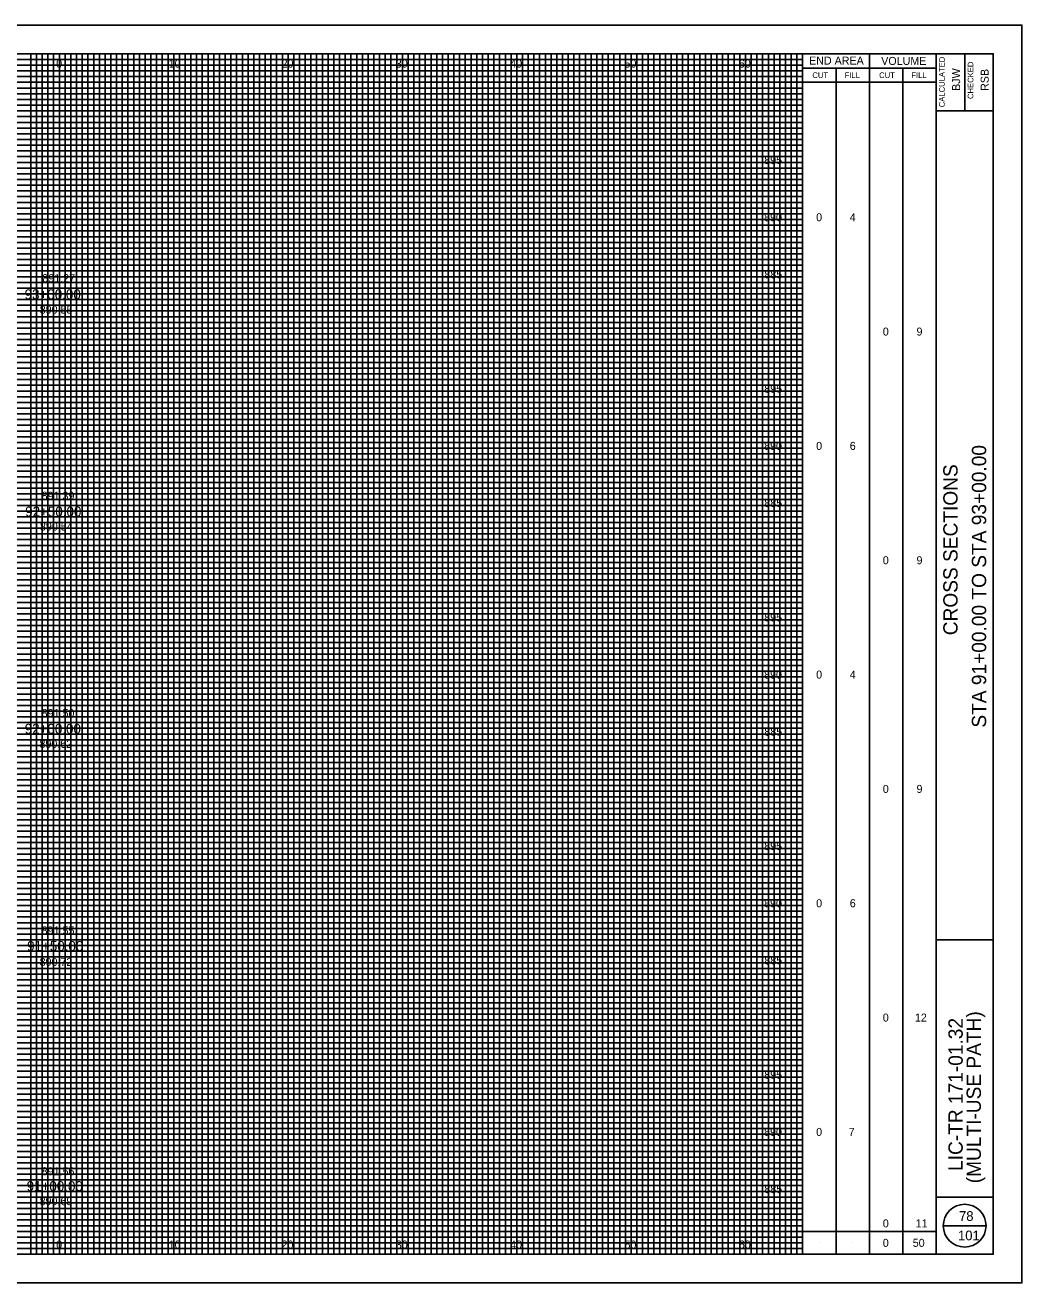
# Model space of a CAD drawing. Extents: x -10 to 160, y -2 to 3672.
# Drawn here: x 72.8 to 160, y 1032.5 to 1142.5 of the extents above; entities that cross this region are included whole.
import ezdxf

# ---------------------------------------------------------------- set-up
doc = ezdxf.new("R2010")
doc.units = 0
for name, color, linetype in [('SH_Border', 7, 'Continuous'), ('SH_Cut_Line', 7, 'Continuous'), ('SH_Data', 7, 'Continuous'), ('SH_Major_Grid_Line', 7, 'Continuous'), ('SH_Minor_Grid_Line', 7, 'Continuous'), ('SH_Text', 7, 'Continuous'), ('TX_P_10', 7, 'Continuous'), ('TX_X_10', 7, 'Continuous')]:
    doc.layers.add(name, color=color, linetype=linetype)

msp = doc.modelspace()

# ---------------------------------------------------------------- linework, layer by layer
at = {"layer": 'SH_Border'}
for p, q in [((152.5, 1035), (152.5, 1140)), ((155, 1140), (155, 1135)), ((152.5, 1135), (157.5, 1135)), ((152.5, 1062.5), (157.5, 1062.5)), ((152.5, 1040), (157.5, 1040))]:
    msp.add_line(p, q, dxfattribs=at)
msp.add_lwpolyline([(0, 1140), (157.5, 1140), (157.5, 1035), (0, 1035)], close=True, dxfattribs=at)
at = {"layer": 'SH_Cut_Line'}
msp.add_lwpolyline([(-10, 1032.5), (160, 1032.5), (160, 1142.5), (-10, 1142.5)], close=True, dxfattribs=at)
at = {"layer": 'SH_Data'}
for p, q in [((140.83, 1035), (140.83, 1140)), ((146.67, 1035), (146.67, 1140)), ((140.83, 1138.75), (152.5, 1138.75)), ((143.75, 1035), (143.75, 1138.75)), ((149.58, 1035), (149.58, 1138.75)), ((140.83, 1137.5), (152.5, 1137.5)), ((153.12, 1037.5), (156.88, 1037.5)), ((140.83, 1037), (152.5, 1037)), ((142.29, 1036), (142.29, 1036)), ((145.21, 1036), (145.21, 1036)), ((148.12, 1036), (148.12, 1036)), ((151.04, 1036), (151.04, 1036))]:
    msp.add_line(p, q, dxfattribs=at)
msp.add_circle((155, 1037.5), 1.87, dxfattribs=at)
at = {"layer": 'SH_Major_Grid_Line'}
for p, q in [((75.83, 1035), (75.83, 1140)), ((80.83, 1035), (80.83, 1140)), ((85.83, 1035), (85.83, 1140)), ((90.83, 1035), (90.83, 1140)), ((95.83, 1035), (95.83, 1140)), ((100.83, 1035), (100.83, 1140)), ((105.83, 1035), (105.83, 1140)), ((110.83, 1035), (110.83, 1140)), ((115.83, 1035), (115.83, 1140)), ((120.83, 1035), (120.83, 1140)), ((125.83, 1035), (125.83, 1140)), ((130.83, 1035), (130.83, 1140)), ((135.83, 1035), (135.83, 1140)), ((5.83, 1135), (140.83, 1135)), ((5.83, 1130), (140.83, 1130)), ((5.83, 1125), (140.83, 1125)), ((5.83, 1120), (140.83, 1120)), ((5.83, 1115), (140.83, 1115)), ((5.83, 1110), (140.83, 1110)), ((5.83, 1105), (140.83, 1105)), ((5.83, 1100), (140.83, 1100)), ((5.83, 1095), (140.83, 1095)), ((5.83, 1090), (140.83, 1090)), ((5.83, 1085), (140.83, 1085)), ((5.83, 1080), (140.83, 1080)), ((5.83, 1075), (140.83, 1075)), ((5.83, 1070), (140.83, 1070)), ((5.83, 1065), (140.83, 1065)), ((5.83, 1060), (140.83, 1060)), ((5.83, 1055), (140.83, 1055)), ((5.83, 1050), (140.83, 1050)), ((5.83, 1045), (140.83, 1045)), ((5.83, 1040), (140.83, 1040))]:
    msp.add_line(p, q, dxfattribs=at)
at = {"layer": 'SH_Minor_Grid_Line'}
for p, q in [((73.33, 1035), (73.33, 1140)), ((73.83, 1035), (73.83, 1140)), ((74.33, 1035), (74.33, 1140)), ((74.83, 1035), (74.83, 1140)), ((75.33, 1035), (75.33, 1140)), ((76.33, 1035), (76.33, 1140)), ((76.83, 1035), (76.83, 1140)), ((77.33, 1035), (77.33, 1140)), ((77.83, 1035), (77.83, 1140)), ((78.33, 1035), (78.33, 1140)), ((78.83, 1035), (78.83, 1140)), ((79.33, 1035), (79.33, 1140)), ((79.83, 1035), (79.83, 1140)), ((80.33, 1035), (80.33, 1140)), ((81.33, 1035), (81.33, 1140)), ((81.83, 1035), (81.83, 1140)), ((82.33, 1035), (82.33, 1140)), ((82.83, 1035), (82.83, 1140)), ((83.33, 1035), (83.33, 1140)), ((83.83, 1035), (83.83, 1140)), ((84.33, 1035), (84.33, 1140)), ((84.83, 1035), (84.83, 1140)), ((85.33, 1035), (85.33, 1140)), ((86.33, 1035), (86.33, 1140)), ((86.83, 1035), (86.83, 1140)), ((87.33, 1035), (87.33, 1140)), ((87.83, 1035), (87.83, 1140)), ((88.33, 1035), (88.33, 1140)), ((88.83, 1035), (88.83, 1140)), ((89.33, 1035), (89.33, 1140)), ((89.83, 1035), (89.83, 1140)), ((90.33, 1035), (90.33, 1140)), ((91.33, 1035), (91.33, 1140)), ((91.83, 1035), (91.83, 1140)), ((92.33, 1035), (92.33, 1140)), ((92.83, 1035), (92.83, 1140)), ((93.33, 1035), (93.33, 1140)), ((93.83, 1035), (93.83, 1140)), ((94.33, 1035), (94.33, 1140)), ((94.83, 1035), (94.83, 1140)), ((95.33, 1035), (95.33, 1140)), ((96.33, 1035), (96.33, 1140)), ((96.83, 1035), (96.83, 1140)), ((97.33, 1035), (97.33, 1140)), ((97.83, 1035), (97.83, 1140)), ((98.33, 1035), (98.33, 1140)), ((98.83, 1035), (98.83, 1140)), ((99.33, 1035), (99.33, 1140)), ((99.83, 1035), (99.83, 1140)), ((100.33, 1035), (100.33, 1140)), ((101.33, 1035), (101.33, 1140)), ((101.83, 1035), (101.83, 1140)), ((102.33, 1035), (102.33, 1140)), ((102.83, 1035), (102.83, 1140)), ((103.33, 1035), (103.33, 1140)), ((103.83, 1035), (103.83, 1140)), ((104.33, 1035), (104.33, 1140)), ((104.83, 1035), (104.83, 1140)), ((105.33, 1035), (105.33, 1140)), ((106.33, 1035), (106.33, 1140)), ((106.83, 1035), (106.83, 1140)), ((107.33, 1035), (107.33, 1140)), ((107.83, 1035), (107.83, 1140)), ((108.33, 1035), (108.33, 1140)), ((108.83, 1035), (108.83, 1140)), ((109.33, 1035), (109.33, 1140)), ((109.83, 1035), (109.83, 1140)), ((110.33, 1035), (110.33, 1140)), ((111.33, 1035), (111.33, 1140)), ((111.83, 1035), (111.83, 1140)), ((112.33, 1035), (112.33, 1140)), ((112.83, 1035), (112.83, 1140)), ((113.33, 1035), (113.33, 1140)), ((113.83, 1035), (113.83, 1140)), ((114.33, 1035), (114.33, 1140)), ((114.83, 1035), (114.83, 1140)), ((115.33, 1035), (115.33, 1140)), ((116.33, 1035), (116.33, 1140)), ((116.83, 1035), (116.83, 1140)), ((117.33, 1035), (117.33, 1140)), ((117.83, 1035), (117.83, 1140)), ((118.33, 1035), (118.33, 1140)), ((118.83, 1035), (118.83, 1140)), ((119.33, 1035), (119.33, 1140)), ((119.83, 1035), (119.83, 1140)), ((120.33, 1035), (120.33, 1140)), ((121.33, 1035), (121.33, 1140)), ((121.83, 1035), (121.83, 1140)), ((122.33, 1035), (122.33, 1140)), ((122.83, 1035), (122.83, 1140)), ((123.33, 1035), (123.33, 1140)), ((123.83, 1035), (123.83, 1140)), ((124.33, 1035), (124.33, 1140)), ((124.83, 1035), (124.83, 1140)), ((125.33, 1035), (125.33, 1140)), ((126.33, 1035), (126.33, 1140)), ((126.83, 1035), (126.83, 1140)), ((127.33, 1035), (127.33, 1140)), ((127.83, 1035), (127.83, 1140)), ((128.33, 1035), (128.33, 1140)), ((128.83, 1035), (128.83, 1140)), ((129.33, 1035), (129.33, 1140)), ((129.83, 1035), (129.83, 1140)), ((130.33, 1035), (130.33, 1140)), ((131.33, 1035), (131.33, 1140)), ((131.83, 1035), (131.83, 1140)), ((132.33, 1035), (132.33, 1140)), ((132.83, 1035), (132.83, 1140)), ((133.33, 1035), (133.33, 1140)), ((133.83, 1035), (133.83, 1140)), ((134.33, 1035), (134.33, 1140)), ((134.83, 1035), (134.83, 1140)), ((135.33, 1035), (135.33, 1140)), ((136.33, 1035), (136.33, 1140)), ((136.83, 1035), (136.83, 1140)), ((137.33, 1035), (137.33, 1140)), ((137.83, 1035), (137.83, 1140)), ((138.33, 1035), (138.33, 1140)), ((138.83, 1035), (138.83, 1140)), ((139.33, 1035), (139.33, 1140)), ((139.83, 1035), (139.83, 1140)), ((140.33, 1035), (140.33, 1140)), ((5.83, 1139.5), (140.83, 1139.5)), ((5.83, 1139), (140.83, 1139)), ((5.83, 1138.5), (140.83, 1138.5)), ((5.83, 1138), (140.83, 1138)), ((5.83, 1137.5), (140.83, 1137.5)), ((5.83, 1137), (140.83, 1137)), ((5.83, 1136.5), (140.83, 1136.5)), ((5.83, 1136), (140.83, 1136)), ((5.83, 1135.5), (140.83, 1135.5)), ((5.83, 1134.5), (140.83, 1134.5)), ((5.83, 1134), (140.83, 1134)), ((5.83, 1133.5), (140.83, 1133.5)), ((5.83, 1133), (140.83, 1133)), ((5.83, 1132.5), (140.83, 1132.5)), ((5.83, 1132), (140.83, 1132)), ((5.83, 1131.5), (140.83, 1131.5)), ((5.83, 1131), (140.83, 1131)), ((5.83, 1130.5), (140.83, 1130.5)), ((5.83, 1129.5), (140.83, 1129.5)), ((5.83, 1129), (140.83, 1129)), ((5.83, 1128.5), (140.83, 1128.5)), ((5.83, 1128), (140.83, 1128)), ((5.83, 1127.5), (140.83, 1127.5)), ((5.83, 1127), (140.83, 1127)), ((5.83, 1126.5), (140.83, 1126.5)), ((5.83, 1126), (140.83, 1126)), ((5.83, 1125.5), (140.83, 1125.5)), ((5.83, 1124.5), (140.83, 1124.5)), ((5.83, 1124), (140.83, 1124)), ((5.83, 1123.5), (140.83, 1123.5)), ((5.83, 1123), (140.83, 1123)), ((5.83, 1122.5), (140.83, 1122.5)), ((5.83, 1122), (140.83, 1122)), ((5.83, 1121.5), (140.83, 1121.5)), ((5.83, 1121), (140.83, 1121)), ((5.83, 1120.5), (140.83, 1120.5)), ((5.83, 1119.5), (140.83, 1119.5)), ((5.83, 1119), (140.83, 1119)), ((5.83, 1118.5), (140.83, 1118.5)), ((5.83, 1118), (140.83, 1118)), ((5.83, 1117.5), (140.83, 1117.5)), ((5.83, 1117), (140.83, 1117)), ((5.83, 1116.5), (140.83, 1116.5)), ((5.83, 1116), (140.83, 1116)), ((5.83, 1115.5), (140.83, 1115.5)), ((5.83, 1114.5), (140.83, 1114.5)), ((5.83, 1114), (140.83, 1114)), ((5.83, 1113.5), (140.83, 1113.5)), ((5.83, 1113), (140.83, 1113)), ((5.83, 1112.5), (140.83, 1112.5)), ((5.83, 1112), (140.83, 1112)), ((5.83, 1111.5), (140.83, 1111.5)), ((5.83, 1111), (140.83, 1111)), ((5.83, 1110.5), (140.83, 1110.5)), ((5.83, 1109.5), (140.83, 1109.5)), ((5.83, 1109), (140.83, 1109)), ((5.83, 1108.5), (140.83, 1108.5)), ((5.83, 1108), (140.83, 1108)), ((5.83, 1107.5), (140.83, 1107.5)), ((5.83, 1107), (140.83, 1107)), ((5.83, 1106.5), (140.83, 1106.5)), ((5.83, 1106), (140.83, 1106)), ((5.83, 1105.5), (140.83, 1105.5)), ((5.83, 1104.5), (140.83, 1104.5)), ((5.83, 1104), (140.83, 1104)), ((5.83, 1103.5), (140.83, 1103.5)), ((5.83, 1103), (140.83, 1103)), ((5.83, 1102.5), (140.83, 1102.5)), ((5.83, 1102), (140.83, 1102)), ((5.83, 1101.5), (140.83, 1101.5)), ((5.83, 1101), (140.83, 1101)), ((5.83, 1100.5), (140.83, 1100.5)), ((5.83, 1099.5), (140.83, 1099.5)), ((5.83, 1099), (140.83, 1099)), ((5.83, 1098.5), (140.83, 1098.5)), ((5.83, 1098), (140.83, 1098)), ((5.83, 1097.5), (140.83, 1097.5)), ((5.83, 1097), (140.83, 1097)), ((5.83, 1096.5), (140.83, 1096.5)), ((5.83, 1096), (140.83, 1096)), ((5.83, 1095.5), (140.83, 1095.5)), ((5.83, 1094.5), (140.83, 1094.5)), ((5.83, 1094), (140.83, 1094)), ((5.83, 1093.5), (140.83, 1093.5)), ((5.83, 1093), (140.83, 1093)), ((5.83, 1092.5), (140.83, 1092.5)), ((5.83, 1092), (140.83, 1092)), ((5.83, 1091.5), (140.83, 1091.5)), ((5.83, 1091), (140.83, 1091)), ((5.83, 1090.5), (140.83, 1090.5)), ((5.83, 1089.5), (140.83, 1089.5)), ((5.83, 1089), (140.83, 1089)), ((5.83, 1088.5), (140.83, 1088.5)), ((5.83, 1088), (140.83, 1088)), ((5.83, 1087.5), (140.83, 1087.5)), ((5.83, 1087), (140.83, 1087)), ((5.83, 1086.5), (140.83, 1086.5)), ((5.83, 1086), (140.83, 1086)), ((5.83, 1085.5), (140.83, 1085.5)), ((5.83, 1084.5), (140.83, 1084.5)), ((5.83, 1084), (140.83, 1084)), ((5.83, 1083.5), (140.83, 1083.5)), ((5.83, 1083), (140.83, 1083)), ((5.83, 1082.5), (140.83, 1082.5)), ((5.83, 1082), (140.83, 1082)), ((5.83, 1081.5), (140.83, 1081.5)), ((5.83, 1081), (140.83, 1081)), ((5.83, 1080.5), (140.83, 1080.5)), ((5.83, 1079.5), (140.83, 1079.5)), ((5.83, 1079), (140.83, 1079)), ((5.83, 1078.5), (140.83, 1078.5)), ((5.83, 1078), (140.83, 1078)), ((5.83, 1077.5), (140.83, 1077.5)), ((5.83, 1077), (140.83, 1077)), ((5.83, 1076.5), (140.83, 1076.5)), ((5.83, 1076), (140.83, 1076)), ((5.83, 1075.5), (140.83, 1075.5)), ((5.83, 1074.5), (140.83, 1074.5)), ((5.83, 1074), (140.83, 1074)), ((5.83, 1073.5), (140.83, 1073.5)), ((5.83, 1073), (140.83, 1073)), ((5.83, 1072.5), (140.83, 1072.5)), ((5.83, 1072), (140.83, 1072)), ((5.83, 1071.5), (140.83, 1071.5)), ((5.83, 1071), (140.83, 1071)), ((5.83, 1070.5), (140.83, 1070.5)), ((5.83, 1069.5), (140.83, 1069.5)), ((5.83, 1069), (140.83, 1069)), ((5.83, 1068.5), (140.83, 1068.5)), ((5.83, 1068), (140.83, 1068)), ((5.83, 1067.5), (140.83, 1067.5)), ((5.83, 1067), (140.83, 1067)), ((5.83, 1066.5), (140.83, 1066.5)), ((5.83, 1066), (140.83, 1066)), ((5.83, 1065.5), (140.83, 1065.5)), ((5.83, 1064.5), (140.83, 1064.5)), ((5.83, 1064), (140.83, 1064)), ((5.83, 1063.5), (140.83, 1063.5)), ((5.83, 1063), (140.83, 1063)), ((5.83, 1062.5), (140.83, 1062.5)), ((5.83, 1062), (140.83, 1062)), ((5.83, 1061.5), (140.83, 1061.5)), ((5.83, 1061), (140.83, 1061)), ((5.83, 1060.5), (140.83, 1060.5)), ((5.83, 1059.5), (140.83, 1059.5)), ((5.83, 1059), (140.83, 1059)), ((5.83, 1058.5), (140.83, 1058.5)), ((5.83, 1058), (140.83, 1058)), ((5.83, 1057.5), (140.83, 1057.5)), ((5.83, 1057), (140.83, 1057)), ((5.83, 1056.5), (140.83, 1056.5)), ((5.83, 1056), (140.83, 1056)), ((5.83, 1055.5), (140.83, 1055.5)), ((5.83, 1054.5), (140.83, 1054.5)), ((5.83, 1054), (140.83, 1054)), ((5.83, 1053.5), (140.83, 1053.5)), ((5.83, 1053), (140.83, 1053)), ((5.83, 1052.5), (140.83, 1052.5)), ((5.83, 1052), (140.83, 1052)), ((5.83, 1051.5), (140.83, 1051.5)), ((5.83, 1051), (140.83, 1051)), ((5.83, 1050.5), (140.83, 1050.5)), ((5.83, 1049.5), (140.83, 1049.5)), ((5.83, 1049), (140.83, 1049)), ((5.83, 1048.5), (140.83, 1048.5)), ((5.83, 1048), (140.83, 1048)), ((5.83, 1047.5), (140.83, 1047.5)), ((5.83, 1047), (140.83, 1047)), ((5.83, 1046.5), (140.83, 1046.5)), ((5.83, 1046), (140.83, 1046)), ((5.83, 1045.5), (140.83, 1045.5)), ((5.83, 1044.5), (140.83, 1044.5)), ((5.83, 1044), (140.83, 1044)), ((5.83, 1043.5), (140.83, 1043.5)), ((5.83, 1043), (140.83, 1043)), ((5.83, 1042.5), (140.83, 1042.5)), ((5.83, 1042), (140.83, 1042)), ((5.83, 1041.5), (140.83, 1041.5)), ((5.83, 1041), (140.83, 1041)), ((5.83, 1040.5), (140.83, 1040.5)), ((5.83, 1039.5), (140.83, 1039.5)), ((5.83, 1039), (140.83, 1039)), ((5.83, 1038.5), (140.83, 1038.5)), ((5.83, 1038), (140.83, 1038)), ((5.83, 1037.5), (140.83, 1037.5)), ((5.83, 1037), (140.83, 1037)), ((5.83, 1036.5), (140.83, 1036.5)), ((5.83, 1036), (140.83, 1036)), ((5.83, 1035.5), (140.83, 1035.5))]:
    msp.add_line(p, q, dxfattribs=at)

# ---------------------------------------------------------------- texts
at = {"layer": 'SH_Data'}
for s, height, p in [('END AREA', 0.7, (141.39, 1139.05)), ('VOLUME', 0.7, (147.7, 1139.02)), ('CUT', 0.5, (141.68, 1137.87)), ('FILL', 0.5, (144.5, 1137.87)), ('CUT', 0.5, (147.52, 1137.87)), ('FILL', 0.5, (150.34, 1137.87)), ('78', 0.85, (154.51, 1037.92)), ('101', 0.85, (154.42, 1036.22))]:
    msp.add_text(s, height=height, dxfattribs=at).set_placement(p)
for s, height, p in [('CALCULATED', 0.5, (153.26, 1135.32)), ('BJW', 0.7, (154.6, 1136.75)), ('CHECKED', 0.5, (155.76, 1136.04)), ('RSB', 0.7, (157.1, 1136.75)), ('STA 91+00.00 TO STA 93+00.00', 1.25, (156.88, 1081.06)), ('CROSS SECTIONS', 1.25, (154.38, 1089.14)), ('(MULTI-USE PATH)', 1.25, (156.42, 1041.21)), ('LIC-TR 171-01.32', 1.25, (154.83, 1042.29))]:
    msp.add_text(s, height=height, rotation=90, dxfattribs=at).set_placement(p)
at = {"layer": 'SH_Text'}
for s, height, p in [('0', 0.7, (75.55, 1138.79)), ('10', 0.7, (85.39, 1138.79)), ('20', 0.7, (95.26, 1138.79)), ('30', 0.7, (105.25, 1138.79)), ('40', 0.7, (115.25, 1138.79)), ('50', 0.7, (125.25, 1138.79)), ('60', 0.7, (135.25, 1138.79)), ('895', 0.7, (137.47, 1130.35)), ('890', 0.7, (137.46, 1125.35)), ('0', 0.7, (142.01, 1125.35)), ('4', 0.7, (144.95, 1125.35)), ('885', 0.7, (137.48, 1120.35)), ('93+00.00', 0.875, (72.79, 1118.52)), ('0', 0.7, (147.84, 1115.35)), ('9', 0.7, (150.79, 1115.35)), ('895', 0.7, (137.47, 1110.35)), ('890', 0.7, (137.46, 1105.35)), ('0', 0.7, (142.01, 1105.35)), ('6', 0.7, (144.95, 1105.35)), ('92+50.00', 0.875, (72.84, 1099.52)), ('885', 0.7, (137.48, 1100.35)), ('0', 0.7, (147.84, 1095.35)), ('9', 0.7, (150.79, 1095.35)), ('895', 0.7, (137.47, 1090.35)), ('890', 0.7, (137.46, 1085.35)), ('0', 0.7, (142.01, 1085.35)), ('4', 0.7, (144.95, 1085.35)), ('92+00.00', 0.875, (72.8, 1080.52)), ('885', 0.7, (137.48, 1080.35)), ('0', 0.7, (147.84, 1075.35)), ('9', 0.7, (150.79, 1075.35)), ('895', 0.7, (137.47, 1070.35)), ('890', 0.7, (137.46, 1065.35)), ('0', 0.7, (142.01, 1065.35)), ('6', 0.7, (144.95, 1065.35)), ('91+50.00', 0.875, (73.01, 1061.52)), ('885', 0.7, (137.48, 1060.35)), ('0', 0.7, (147.84, 1055.35)), ('12', 0.7, (150.65, 1055.35)), ('895', 0.7, (137.47, 1050.35)), ('890', 0.7, (137.46, 1045.35)), ('0', 0.7, (142.01, 1045.35)), ('7', 0.7, (144.86, 1045.35)), ('91+00.00', 0.875, (72.97, 1040.52)), ('885', 0.7, (137.48, 1040.35)), ('0', 0.7, (147.84, 1037.35)), ('11', 0.7, (150.71, 1037.35)), ('0', 0.7, (75.55, 1035.5)), ('10', 0.7, (85.39, 1035.5)), ('20', 0.7, (95.26, 1035.5)), ('30', 0.7, (105.25, 1035.5)), ('40', 0.7, (115.25, 1035.5)), ('50', 0.7, (125.25, 1035.5)), ('60', 0.7, (135.25, 1035.5)), ('0', 0.7, (147.84, 1035.65)), ('50', 0.7, (150.46, 1035.65))]:
    msp.add_text(s, height=height, dxfattribs=at).set_placement(p)
at = {"layer": 'TX_P_10'}
for s, p in [('891.27', (74.34, 1120.02)), ('891.39', (74.28, 1100.99)), ('891.50', (74.28, 1081.98)), ('891.55', (74.28, 1062.97)), ('891.56', (74.28, 1041.91))]:
    msp.add_text(s, height=0.7, dxfattribs=at).set_placement(p)
at = {"layer": 'TX_X_10'}
for s, p in [('890.55', (74.11, 1117.27)), ('890.54', (74.13, 1098.3)), ('890.62', (74.09, 1079.29)), ('890.72', (74.1, 1060.22)), ('890.69', (74.1, 1039.29))]:
    msp.add_text(s, height=0.7, dxfattribs=at).set_placement(p)

doc.saveas('drawing.dxf')
